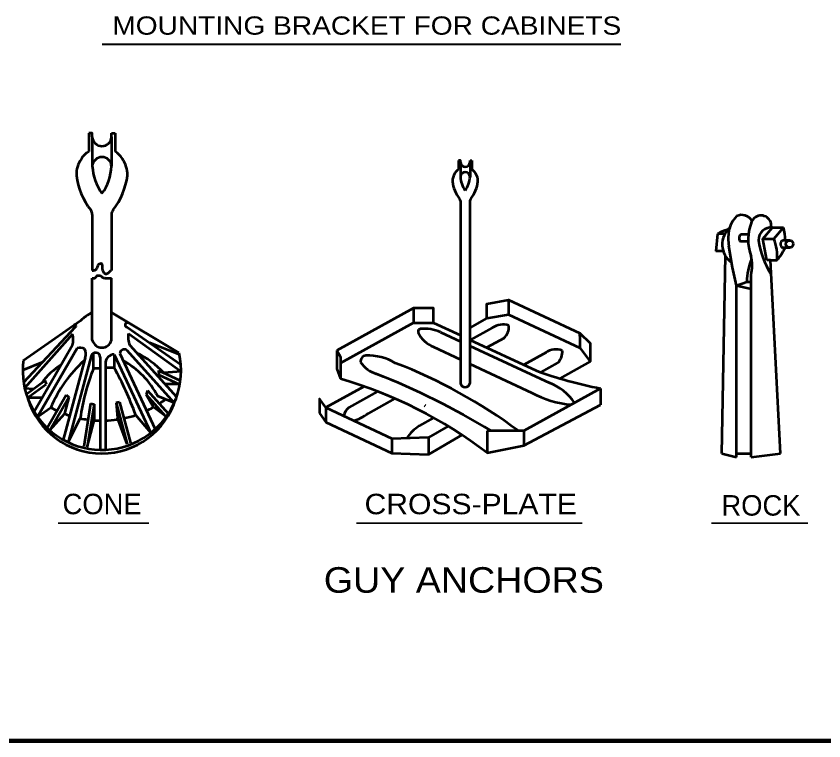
# Model space of a CAD drawing. Extents: x 14808 to 15663, y 10944 to 11488.
# Drawn here: x 15031.3 to 15163.9, y 10955.6 to 11074.7 of the extents above; entities that cross this region are included whole.
import ezdxf
from ezdxf.enums import TextEntityAlignment as Align

# ---------------------------------------------------------------- set-up
doc = ezdxf.new("R2010")
doc.units = 0
doc.header["$LTSCALE"] = 1.2
doc.layers.add('1', color=7, linetype='Continuous', lineweight=53)

msp = doc.modelspace()

# ---------------------------------------------------------------- linework, layer by layer
at = {"layer": '1', "lineweight": 40}
msp.add_line((15045.476, 11070.058), (15130.588, 11070.058), dxfattribs=at)
at = {"layer": '1'}
for p, q in [((15043.236, 11055.444), (15043.236, 11052.444)), ((15047.002, 11054.835), (15047.002, 11055.444)), ((15047.002, 11055.444), (15047.602, 11055.444)), ((15047.602, 11055.444), (15047.602, 11052.444)), ((15043.836, 11054.842), (15043.836, 11050.042)), ((15047.002, 11054.835), (15047.002, 11050.035)), ((15103.975, 11051), (15103.975, 11049.5)), ((15104.275, 11050.699), (15104.275, 11048.299)), ((15105.858, 11050.695), (15105.858, 11051)), ((15105.858, 11051), (15106.158, 11051)), ((15105.858, 11050.695), (15105.858, 11048.296)), ((15106.158, 11051), (15106.158, 11049.5)), ((15104.275, 11044.327), (15104.275, 11014.327)), ((15105.844, 11044.327), (15105.844, 11014.327)), ((15043.836, 11042.098), (15043.836, 11032.928)), ((15046.975, 11042.098), (15046.975, 11032.928)), ((15146.48, 11038.938), (15146.193, 11036.081)), ((15147.68, 11038.938), (15146.48, 11038.938)), ((15151.559, 11038.793), (15150.267, 11038.793)), ((15151.473, 11037.644), (15150.267, 11037.644)), ((15158.346, 11037.852), (15157.146, 11037.852)), ((15147.387, 11036.081), (15146.193, 11036.081)), ((15158.346, 11036.652), (15157.146, 11036.652)), ((15147.214, 11002.821), (15147.781, 11035.335)), ((15155.181, 11034.578), (15154.581, 11034.578)), ((15156.845, 11002.822), (15155.181, 11034.578)), ((15155.181, 11034.578), (15156.264, 11034.578)), ((15043.835, 11021.449), (15043.835, 11031.649)), ((15046.977, 11021.449), (15046.977, 11031.649)), ((15152.014, 11002.221), (15152.014, 11032.221)), ((15149.614, 11002.221), (15149.614, 11030.421)), ((15149.614, 11030.421), (15152.014, 11029.911)), ((15112.182, 11028.078), (15123.873, 11022.627)), ((15096.562, 11026.716), (15083.968, 11019.735)), ((15046.957, 11026.022), (15058.035, 11019.365)), ((15108.637, 11025.053), (15105.844, 11023.506)), ((15108.637, 11025.053), (15112.182, 11025.678)), ((15112.182, 11025.678), (15123.873, 11020.227)), ((15041.869, 11024.645), (15032.5, 11018.084)), ((15041.017, 11023.622), (15032.541, 11014.532)), ((15049.578, 11023.622), (15058.358, 11017.474)), ((15096.562, 11024.316), (15084.568, 11017.667)), ((15099.863, 11024.316), (15104.267, 11022.262)), ((15109.509, 11023.479), (15105.922, 11021.49)), ((15040.597, 11022.422), (15032.718, 11013.586)), ((15049.781, 11022.579), (15058.398, 11016.319)), ((15101.012, 11022.787), (15104.287, 11021.26)), ((15123.873, 11022.627), (15123.873, 11020.227)), ((15058.045, 11019.1), (15053.295, 11021.019)), ((15105.844, 11021.527), (15116.72, 11016.455)), ((15111.436, 11021.803), (15108.611, 11020.237)), ((15040.597, 11020.622), (15034.29, 11009.697)), ((15041.36, 11020.142), (15034.845, 11008.859)), ((15049.514, 11019.815), (15057.285, 11011.184)), ((15049.998, 11020.622), (15057.641, 11012.133)), ((15099.871, 11020.34), (15104.275, 11018.287)), ((15105.822, 11020.544), (15118.895, 11014.448)), ((15042.645, 11018.55), (15039.043, 11005.109)), ((15043.654, 11018.839), (15039.862, 11004.687)), ((15044.054, 11016.853), (15044.054, 11019.38)), ((15045.147, 11018.657), (15045.147, 11003.449)), ((15047.438, 11019.106), (15053.434, 11006.248)), ((15048.351, 11019.278), (15054.152, 11006.838)), ((15118.37, 11019.44), (15114.692, 11017.401)), ((15032.378, 11016.528), (15035.626, 11017.841)), ((15044.054, 11016.853), (15045.147, 11016.853)), ((15045.999, 11017.525), (15045.999, 11003.449)), ((15105.844, 11017.555), (15116.01, 11012.814)), ((15120.227, 11017.726), (15117.46, 11016.192)), ((15054.704, 11016.464), (15058.126, 11014.868)), ((15054.704, 11016.464), (15054.737, 11015.787)), ((15054.737, 11015.787), (15058.09, 11014.223)), ((15058.398, 11016.319), (15055.551, 11016.069)), ((15032.912, 11012.522), (15036.06, 11014.809)), ((15033.264, 11012.036), (15036.256, 11014.21)), ((15036.06, 11014.809), (15036.256, 11014.21)), ((15058.09, 11014.223), (15055.759, 11014.223)), ((15032.718, 11013.586), (15034.198, 11013.456)), ((15052.884, 11013.175), (15052.658, 11012.529)), ((15052.884, 11013.175), (15056.282, 11009.402)), ((15090.68, 11013.042), (15085.957, 11010.424)), ((15127.269, 11013.522), (15127.269, 11010.822)), ((15033.264, 11012.036), (15035.676, 11012.036)), ((15036.398, 11007.069), (15039.526, 11012.488)), ((15036.851, 11006.655), (15039.984, 11012.08)), ((15039.984, 11012.08), (15039.27, 11009.417)), ((15039.526, 11012.488), (15039.984, 11012.08)), ((15052.658, 11012.529), (15055.836, 11009)), ((15053.871, 11010.451), (15052.658, 11012.529)), ((15057.285, 11011.184), (15054.581, 11012.246)), ((15093.523, 11011.874), (15089.114, 11009.43)), ((15034.845, 11008.859), (15037.03, 11010.394)), ((15043.533, 11011.033), (15042.42, 11004.003)), ((15044.126, 11010.94), (15043.013, 11003.909)), ((15043.533, 11011.033), (15044.126, 11010.94)), ((15044.126, 11010.94), (15044.126, 11008.275)), ((15048.319, 11011.295), (15047.74, 11011.139)), ((15047.74, 11011.139), (15049.559, 11004.35)), ((15047.74, 11011.139), (15047.953, 11008.698)), ((15048.319, 11011.295), (15050.12, 11004.576)), ((15055.836, 11009), (15053.871, 11010.451)), ((15082.15, 11010.372), (15093.026, 11005.301)), ((15082.15, 11010.372), (15082.15, 11007.972)), ((15036.851, 11006.655), (15039.303, 11009.388)), ((15053.434, 11006.248), (15050.965, 11009.163)), ((15039.862, 11004.687), (15041.855, 11008.614)), ((15043.013, 11003.909), (15044.126, 11008.275)), ((15049.559, 11004.35), (15047.953, 11008.698)), ((15099.871, 11008.729), (15097.524, 11007.37)), ((15102.257, 11007.338), (15099.053, 11005.482)), ((15114.674, 11006.541), (15114.674, 11004.141)), ((15093.026, 11005.301), (15099.022, 11005.51)), ((15093.026, 11005.301), (15093.026, 11002.9)), ((15104.589, 11005.915), (15099.022, 11002.691)), ((15099.022, 11005.51), (15099.022, 11002.691)), ((15093.026, 11002.9), (15099.022, 11002.691)), ((15147.214, 11002.821), (15149.614, 11002.221)), ((15149.614, 11002.821), (15152.014, 11002.821)), ((15152.014, 11002.221), (15156.845, 11002.822))]:
    msp.add_line(p, q, dxfattribs=at)
at = {"layer": '1', "lineweight": 13}
for p, q in [((15120.584, 11015.179), (15120.388, 11015.066)), ((15098.347, 11010.483), (15098.602, 11010.895))]:
    msp.add_line(p, q, dxfattribs=at)
at = {"layer": '1', "lineweight": 35}
for p, q in [((15038.213, 10991.384), (15053.12, 10991.384)), ((15087.224, 10991.384), (15124.263, 10991.384)), ((15145.494, 10991.384), (15161.303, 10991.384))]:
    msp.add_line(p, q, dxfattribs=at)
at = {"layer": '1', "lineweight": 158}
msp.add_line((15656.868, 10955.64), (14865.268, 10955.64), dxfattribs=at)
at = {"layer": '1'}
for points in [[(15043.836, 11054.842), (15043.836, 11055.444), (15043.236, 11055.444)], [(15104.275, 11050.699), (15104.275, 11051), (15103.975, 11051)], [(15154.581, 11034.578), (15153.956, 11038.123), (15155.756, 11038.123), (15157.298, 11039.962)], [(15153.956, 11038.123), (15155.498, 11039.962), (15157.298, 11039.962)], [(15149.614, 11030.421), (15148.948, 11033.416), (15148.323, 11036.961)], [(15149.614, 11030.421), (15151.305, 11031.036), (15152.014, 11031.036)], [(15108.637, 11025.053), (15108.637, 11027.453), (15112.182, 11028.078), (15112.182, 11025.678)], [(15123.884, 11022.139), (15123.873, 11022.627), (15125.6, 11020.96), (15125.6, 11017.96)], [(15083.968, 11019.735), (15084.568, 11018.695), (15084.568, 11015.096)], [(15083.968, 11019.735), (15083.968, 11016.735), (15084.568, 11015.096)], [(15123.873, 11020.227), (15125.6, 11017.96), (15120.584, 11015.179)], [(15047.438, 11019.106), (15047.438, 11016.938), (15045.999, 11016.938)], [(15088.448, 11013.863), (15082.15, 11010.372), (15081.118, 11011.846), (15081.118, 11009.446)], [(15127.269, 11013.522), (15114.674, 11006.541), (15108.674, 11006.541)], [(15108.674, 11006.541), (15108.674, 11002.941), (15114.674, 11004.141), (15127.269, 11010.822)], [(15081.118, 11009.446), (15082.15, 11007.972), (15093.026, 11002.9)]]:
    msp.add_lwpolyline(points, dxfattribs=at)
msp.add_lwpolyline([(15099.863, 11024.316), (15099.863, 11026.716), (15096.562, 11026.716), (15096.562, 11024.316)], close=True, dxfattribs=at)
msp.add_circle((15158.324, 11037.257), 0.6, dxfattribs=at)
for centre, radius, start, end in [((15045.419, 11054.929), 1.586, 183.14868, 356.60343), ((15044.755, 11049.725), 3.115, 119.19068, 150.80932), ((15045.419, 11049.948), 1.586, 3.15687, 176.59703), ((15046.056, 11049.725), 3.115, 29.19068, 60.80932), ((15045.607, 11048.689), 4.39, 144.42176, 182.06662), ((15052.49, 11050.55), 8.669, 183.35766, 215.34932), ((15038.348, 11050.543), 8.669, 324.65068, 356.64234), ((15045.204, 11048.689), 4.39, 357.93338, 35.57824), ((15105.066, 11050.742), 0.793, 183.14868, 356.60343), ((15105.16, 11047.622), 2.195, 144.42176, 182.06662), ((15104.734, 11048.14), 1.557, 119.19068, 150.80932), ((15105.066, 11048.252), 0.793, 3.15687, 176.59703), ((15105.385, 11048.14), 1.557, 29.19068, 60.80932), ((15104.959, 11047.622), 2.195, 357.93338, 35.57824), ((15052.352, 11049.812), 11.207, 186.56595, 218.44896), ((15038.459, 11049.812), 11.207, 321.55104, 353.43405), ((15108.533, 11048.184), 5.603, 186.56595, 218.44896), ((15108.602, 11048.553), 4.334, 183.35766, 215.34932), ((15101.531, 11048.549), 4.334, 324.65068, 356.64234), ((15101.586, 11048.184), 5.603, 321.55104, 353.43405), ((15103.675, 11044.327), 0.6, 0, 38.44896), ((15106.444, 11044.327), 0.6, 141.55104, 180), ((15042.636, 11042.098), 1.2, 0, 38.44896), ((15048.175, 11042.098), 1.2, 141.55104, 180), ((15150.478, 11040.139), 1.891, 27.27122, 117.20122), ((15153.357, 11038.287), 5.148, 136.6517, 167.95246), ((15159.359, 11037.974), 7.844, 156.78247, 200.56684), ((15156.328, 11038.045), 5.157, 137.75004, 144.12043), ((15153.634, 11040.244), 1.694, 354.19595, 131.52888), ((15148.731, 11035.508), 4.103, 98.89517, 123.27294), ((15150.871, 11037.201), 3.61, 130.0252, 235.18403), ((15159.764, 11038.161), 11.504, 174.01262, 185.98737), ((15155.283, 11037.897), 2.076, 84.04734, 179.89391), ((15150.927, 11038.039), 6.654, 358.55245, 16.7912), ((15150.822, 11038.219), 0.799, 133.97941, 226.02058), ((15148.149, 11035.224), 8.14, 355.44941, 20.86555), ((15167.388, 11039.908), 14.322, 188.05699, 211.90806), ((15157.571, 11037.252), 0.736, 125.33791, 234.66209), ((15147.68, 11041.48), 11.014, 321.19678, 333.99968), ((15161.33, 11030.933), 10.026, 157.16459, 179.40955), ((15145.323, 11033.721), 6.857, 347.36391, 12.63609), ((15047.508, 11018.685), 8.205, 116.58954, 133.41014), ((15040.964, 11023.814), 0.199, 285.47106, 119.84894), ((15049.565, 11023.977), 0.355, 72.34222, 272.05741), ((15111.236, 11021.053), 2.978, 70.73362, 125.44724), ((15109.758, 11023.63), 2.473, 312.2199, 5.43688), ((15037.106, 11021.522), 3.605, 345.54353, 14.45647), ((15052.507, 11021.891), 2.812, 165.83192, 206.84011), ((15097.788, 11022.877), 0.46, 85.12517, 207.35251), ((15101.601, 11024.685), 4.677, 204.55458, 248.28903), ((15098.222, 11016.12), 7.227, 67.29002, 93.88305), ((15045.406, 11021.877), 1.628, 195.24731, 344.75269), ((15041.776, 11018.508), 1.687, 63.18198, 104.27978), ((15041.187, 11019.177), 1.588, 336.72582, 31.75765), ((15049.087, 11019.211), 0.739, 54.79805, 174.78973), ((15120.022, 11016.973), 2.978, 70.73362, 125.44724), ((15118.543, 11019.55), 2.473, 312.2199, 5.43688), ((15045.399, 11016.449), 13, 172.76636, 12.86069), ((15044.385, 11018.623), 0.762, 2.53809, 163.55027), ((15047.415, 11017.681), 1.425, 89.05434, 186.28866), ((15045.238, 11006.792), 13.871, 41.97741, 64.76098), ((15088.836, 11017.975), 0.958, 94.88611, 188.90189), ((15089.089, 11010.192), 8.744, 59.08543, 92.19679), ((15045.98, 11006.314), 13.277, 122.96526, 142.37873), ((15056.394, 11002.431), 20.938, 131.72438, 157.64771), ((15074.803, 11004.232), 33.238, 157.68458, 172.42454), ((14993.415, 10987.747), 61.405, 20.41201, 28.38414), ((15042.229, 11005.916), 13.88, 27.13242, 61.23505), ((15091.672, 11020.287), 4.512, 213.03543, 254.05828), ((15064.345, 10940.826), 82.24, 53.04115, 69.17556), ((15044.01, 10898.87), 125.946, 58.74865, 68.37109), ((15141.212, 11084.111), 71.953, 250.09888, 258.8259), ((15064.57, 10945.45), 72.46, 52.50633, 73.9788), ((15105.059, 11014.54), 0.813, 195.19877, 344.80123), ((15115.733, 11006.265), 8.773, 33.93256, 68.86981), ((15045.399, 11015.562), 12.713, 196.98242, 343.01758), ((15045.399, 11025.649), 17.4, 302.79246, 306.95206), ((15123.754, 11026.865), 16.044, 241.1379, 265.46719), ((15045.399, 11025.649), 17.4, 241.25089, 244.7288), ((15045.399, 11025.649), 17.4, 294.68825, 298.86032), ((15087.638, 11008.454), 2.59, 130.48502, 167.67788), ((15045.399, 11025.649), 17.4, 249.43644, 252.21677), ((15045.399, 11025.649), 17.4, 282.12514, 288.50814), ((15085.312, 11014.209), 6.107, 282.65039, 308.50672), ((15045.399, 11025.649), 17.4, 258.07352, 262.19692), ((15045.399, 11025.649), 17.4, 265.78587, 269.16942), ((15045.399, 11025.649), 17.4, 271.8867, 278.3643), ((15100.915, 11001.785), 6.534, 121.25992, 146.56057)]:
    msp.add_arc(centre, radius, start, end, dxfattribs=at)
for points in [[(15043.836, 11032.928), (15044.365, 11033.007), (15044.673, 11033.47), (15044.981, 11033.984), (15045.29, 11034.087), (15045.444, 11033.573), (15045.444, 11033.162), (15045.598, 11032.75), (15045.907, 11032.391), (15046.369, 11032.442), (15046.832, 11032.853), (15046.975, 11032.928)], [(15043.835, 11031.649), (15044.171, 11031.666), (15044.408, 11031.785), (15044.626, 11032.061), (15044.843, 11032.101), (15045.238, 11032.002), (15045.456, 11031.824), (15045.95, 11031.666), (15046.325, 11031.646), (15046.977, 11031.649)]]:
    msp.add_spline(points, degree=3, dxfattribs=at)

# ---------------------------------------------------------------- texts
at = {"layer": '1', "width": 1.15}
msp.add_text('MOUNTING BRACKET FOR CABINETS', height=3, dxfattribs=at).set_placement((15047.121, 11071.641))
at = {"layer": '1'}
for s, p in [('CONE', (15045.441, 10992.866)), ('ROCK', (15153.624, 10992.64))]:
    msp.add_text(s, height=3.36, dxfattribs=at).set_placement(p, align=Align.CENTER)
at = {"layer": '1', "width": 1.1}
for s, height, p in [('CROSS-PLATE', 3.36, (15105.969, 10992.866)), ('GUY ANCHORS', 4.2, (15104.84, 10979.969))]:
    msp.add_text(s, height=height, dxfattribs=at).set_placement(p, align=Align.CENTER)

doc.saveas('drawing.dxf')
